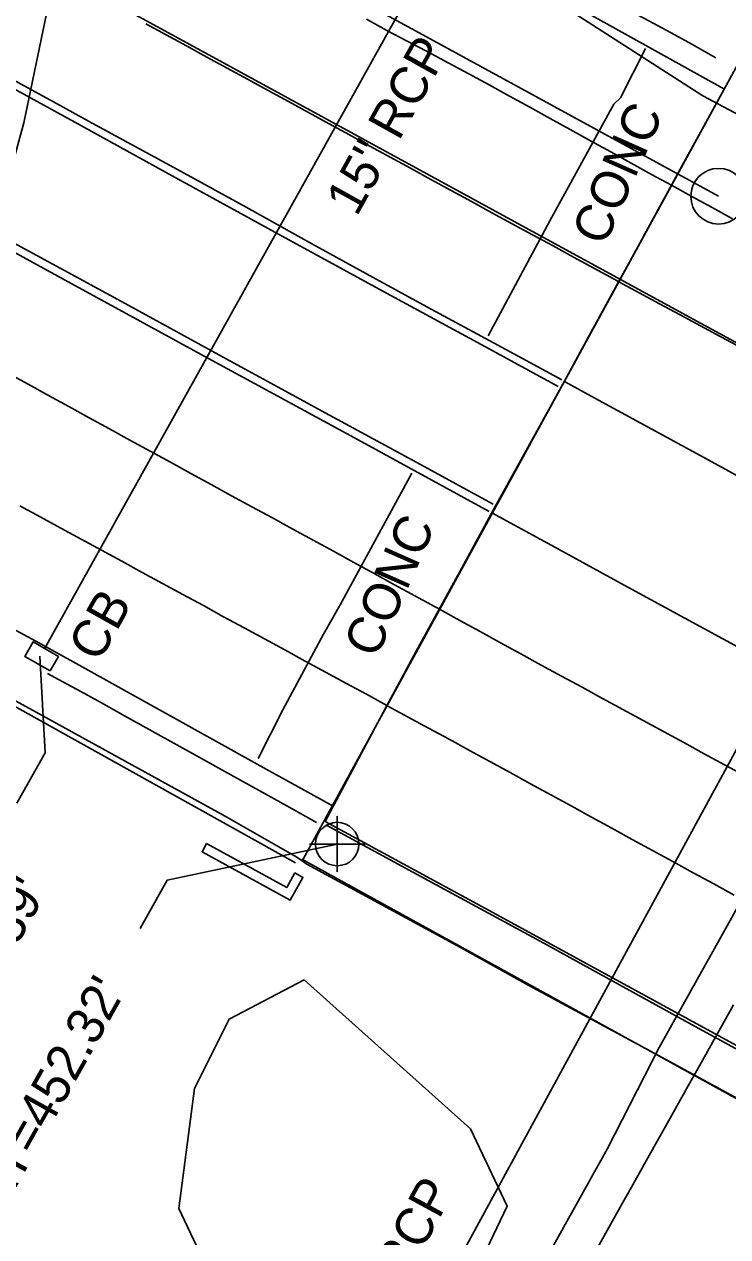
# Model space of a CAD drawing. Extents: x 2074109 to 2077820, y 741079 to 746031.
# Drawn here: x 2075369.9 to 2075445.8, y 743340.7 to 743471.4 of the extents above; entities that cross this region are included whole.
import ezdxf

# ---------------------------------------------------------------- set-up
doc = ezdxf.new("R2010")
doc.units = 0
for name, color, linetype in [('Exist Guardrail', 7, 'Continuous'), ('Exist Horizontal Alignment', 7, 'Continuous'), ('Exist Horizontal Alignment Point', 7, 'Continuous'), ('Exist Roads Change in Surface', 7, 'Continuous'), ('Exist Roads Change in Surface Text', 7, 'Continuous'), ('Exist Roads Curbs', 7, 'Continuous'), ('Exist Roads EOP', 7, 'Continuous'), ('Exist Roads EOP Other', 7, 'Continuous'), ('Exist Roads EOT', 7, 'Continuous'), ('Exist Structure Major Bridge Seam', 7, 'Continuous'), ('Exist Structure Major Bridge Seat Cogo Point CELL', 7, 'Continuous'), ('Exist Structure Major Bridge Seat Leader', 7, 'Continuous'), ('Exist Structure Major Bridge Seat Top Elevation', 7, 'Continuous'), ('Exist Structure Major Deck Tunnel Box Culvert', 7, 'Continuous'), ('Exist Structure Minor Catch Basin', 7, 'Continuous'), ('Exist Structure Minor Catch Basin Leader', 7, 'Continuous'), ('Exist Structure Minor Catch Basin Text', 7, 'Continuous'), ('Exist Structure Minor Head and End Wall', 7, 'Continuous'), ('Exist Structure Minor Pipes RCP 15 Inch', 7, 'Continuous'), ('Exist Structure Minor Pipes RCP 15 Inch Invert', 7, 'Continuous'), ('Exist Structure Minor Pipes RCP 15 Inch Text', 7, 'Continuous'), ('Exist Structure Minor Pipes RCP 36 Inch', 7, 'Continuous'), ('Exist Structure Minor Pipes RCP 36 Inch Text', 7, 'Continuous'), ('Exist Utilities Telephone UG Conduit SUE LOS B', 7, 'Continuous'), ('Exist Utilities Telephone UG FO SUE LOS B', 7, 'Continuous'), ('Exist Vegetation Woods Line', 7, 'Continuous')]:
    doc.layers.add(name, color=color, linetype=linetype)

msp = doc.modelspace()

# ---------------------------------------------------------------- linework, layer by layer
at = {"layer": 'Exist Guardrail'}
msp.add_lwpolyline([(2075399.18, 743381.02), (2075362.55, 743401.44), (2075326.57, 743419.67), (2075290.61, 743437.99), (2075249.28, 743458.82), (2075221.14, 743472.97)], dxfattribs=at)
at = {"layer": 'Exist Horizontal Alignment'}
for p, q in [((2074769.18, 743807.11), (2075920.37, 743178.35)), ((2075444.78, 743452.87), (2075373.12, 743492))]:
    msp.add_line(p, q, dxfattribs=at)
at = {"layer": 'Exist Horizontal Alignment Point'}
msp.add_circle((2075444.78, 743452.87), 3, dxfattribs=at)
at = {"layer": 'Exist Roads Change in Surface'}
for points in [[(2075419.96, 743437.84), (2075426.6, 743450.23), (2075433.48, 743462.79), (2075434.19, 743463.49), (2075436.91, 743468.78)], [(2075411.73, 743423.01), (2075404, 743408.84), (2075402.21, 743405.67), (2075397.81, 743397.52), (2075395.17, 743392.28)]]:
    msp.add_lwpolyline(points, dxfattribs=at)
at = {"layer": 'Exist Roads Curbs'}
for points in [[(2075175.25, 743570.29), (2075183.74, 743565.61), (2075195.08, 743559.37), (2075206.25, 743553.25), (2075217.16, 743547.3), (2075227.86, 743541.4), (2075238.69, 743535.42), (2075250.44, 743529.02), (2075262.94, 743522.24), (2075275.65, 743515.31), (2075288.48, 743508.29), (2075301.25, 743501.33), (2075314, 743494.4), (2075326.85, 743487.38), (2075339.73, 743480.33), (2075352.49, 743473.37), (2075365.03, 743466.54), (2075375.41, 743460.85), (2075385.9, 743455.07), (2075397.36, 743448.78), (2075408.6, 743442.64), (2075420.04, 743436.42), (2075427.48, 743432.37)], [(2075420.48, 743419.7), (2075420.02, 743419.95), (2075412.25, 743424.18), (2075402.85, 743429.29), (2075391.33, 743435.57), (2075380.42, 743441.51), (2075371.29, 743446.47), (2075364.58, 743450.13), (2075360.37, 743452.44), (2075354.18, 743455.85), (2075344.34, 743461.27), (2075334.17, 743466.84), (2075325, 743471.86), (2075315.82, 743476.88), (2075306.25, 743482.12), (2075297.05, 743487.13), (2075288.5, 743491.79), (2075279.47, 743496.71), (2075269.54, 743502.14), (2075259.42, 743507.68), (2075249.44, 743513.13), (2075240.01, 743518.27), (2075231.36, 743522.98)], [(2075417.69, 743482.38), (2075418.53, 743481.88), (2075419.49, 743481.34), (2075420.55, 743480.75), (2075421.73, 743480.12), (2075423.1, 743479.4), (2075424.73, 743478.52), (2075426.61, 743477.5), (2075428.76, 743476.34), (2075430.99, 743475.12), (2075433.14, 743473.96), (2075435.22, 743472.85), (2075436.72, 743472.05), (2075438.18, 743471.28), (2075440.06, 743470.26), (2075441.88, 743469.26), (2075443.64, 743468.26), (2075444.49, 743467.77)], [(2075372.45, 743401.45), (2075374.11, 743400.55), (2075376.06, 743399.49), (2075378.27, 743398.27), (2075380.76, 743396.89), (2075384.07, 743395.06), (2075388.73, 743392.46), (2075391.57, 743390.88), (2075398.26, 743387.16), (2075401.43, 743385.38)]]:
    msp.add_lwpolyline(points, dxfattribs=at)
at = {"layer": 'Exist Roads EOP'}
for points in [[(2075559.5, 743577.98), (2075554.8, 743568.73), (2075547.03, 743553.55), (2075539.18, 743539.38), (2075530.34, 743523.8), (2075517.96, 743501.62), (2075504.54, 743477.52), (2075492.04, 743456), (2075482.7, 743440.16), (2075465.16, 743408.97), (2075448.94, 743380.02), (2075438.36, 743361.14), (2075432.82, 743350.24), (2075423.13, 743332.91), (2075408.43, 743306.71), (2075394.81, 743282.87), (2075378.9, 743255.03), (2075364.05, 743228.71), (2075347.68, 743199.79), (2075332.2, 743172.4), (2075317.22, 743145.53), (2075301.28, 743116.93)], [(2075445.35, 743464.44), (2075424.96, 743475.81), (2075414.28, 743481.69), (2075407.34, 743485.74), (2075396.65, 743492.12), (2075387.15, 743498.07), (2075378.48, 743503.71), (2075370.8, 743508.8), (2075365.1, 743512.76), (2075359.72, 743516.76), (2075352.43, 743522.45), (2075343.87, 743529.41), (2075336.63, 743535.65), (2075330.1, 743541.75), (2075323.4, 743548.45), (2075316.7, 743555.85), (2075309.06, 743565.08), (2075302.29, 743573.79)], [(2075427.87, 743433.07), (2075420.6, 743437.03), (2075413.35, 743440.97), (2075407.54, 743444.13), (2075401.03, 743447.72), (2075393.85, 743451.69), (2075386.06, 743455.97), (2075377.27, 743460.76), (2075372.37, 743463.44), (2075361.94, 743469.13), (2075353.05, 743473.99), (2075345.6, 743478.07), (2075336.55, 743483.02), (2075325.74, 743488.95), (2075315.16, 743494.76), (2075305.01, 743500.33), (2075294.55, 743506.07), (2075283.83, 743511.92), (2075274.03, 743517.26), (2075265.18, 743522.07), (2075256.27, 743526.92), (2075247.15, 743531.89), (2075238.05, 743536.86)], [(2075284.45, 743493.05), (2075292.25, 743488.78), (2075300.07, 743484.51), (2075307.84, 743480.26), (2075315.47, 743476.09), (2075323.04, 743471.96), (2075330.63, 743467.8), (2075338.47, 743463.51), (2075346.79, 743458.93), (2075355.33, 743454.23), (2075363.85, 743449.56), (2075374.69, 743443.65), (2075390.21, 743435.18), (2075405.93, 743426.61), (2075417.36, 743420.37), (2075420.04, 743418.91)], [(2075230.5, 743481.8), (2075255.92, 743467.85), (2075272.88, 743458.6), (2075289.2, 743449.66), (2075307.46, 743439.62), (2075321.84, 743431.78), (2075340.07, 743421.91), (2075360.95, 743410.47), (2075371.58, 743404.7), (2075377.48, 743401.43), (2075396.01, 743391.13), (2075403.25, 743387.13)], [(2075532.37, 743375.92), (2075523.96, 743380.52), (2075515.49, 743385.17), (2075506.78, 743389.94), (2075497.65, 743394.92), (2075489.69, 743399.26), (2075484.47, 743402.11), (2075479.33, 743404.92), (2075471.62, 743409.15), (2075462.56, 743414.11), (2075453.37, 743419.14), (2075443.26, 743424.67), (2075431.45, 743431.12), (2075428.16, 743432.91)], [(2075420.33, 743418.75), (2075426.41, 743415.43), (2075434.98, 743410.75), (2075445.24, 743405.16), (2075459.35, 743397.48), (2075472.97, 743390.06), (2075481.74, 743385.26), (2075488.52, 743381.56), (2075496.16, 743377.42), (2075504.19, 743373.06), (2075512.14, 743368.72), (2075520.42, 743364.18), (2075529.4, 743359.25), (2075538.28, 743354.38)]]:
    msp.add_lwpolyline(points, dxfattribs=at)
at = {"layer": 'Exist Roads EOP Other'}
for points in [[(2075366.87, 743399.63), (2075391.52, 743386.11), (2075399.31, 743381.63), (2075400.42, 743380.9), (2075400.42, 743380.9), (2075417.05, 743371.88), (2075424.34, 743367.81), (2075437.43, 743360.73), (2075449.67, 743354.08), (2075462.75, 743347.04), (2075479.55, 743337.75), (2075493.27, 743330.26), (2075511.78, 743320.13), (2075532.97, 743308.52), (2075543.32, 743302.78), (2075555.58, 743296.07), (2075570.56, 743287.96), (2075581.08, 743282.13), (2075591.83, 743276.3), (2075602.54, 743270.44)], [(2075618.54, 743267.07), (2075601.14, 743276.62), (2075583.53, 743286.17), (2075564.08, 743296.86), (2075539.72, 743310.19), (2075523.4, 743319.09), (2075507.55, 743327.8), (2075492.26, 743336.14), (2075475.25, 743345.43), (2075460.95, 743353.21), (2075441.94, 743363.59), (2075425.56, 743372.59), (2075411.83, 743380.02), (2075402.45, 743385.14)]]:
    msp.add_lwpolyline(points, dxfattribs=at)
at = {"layer": 'Exist Roads EOT'}
for points in [[(2075383.05, 743471.46), (2075385.24, 743470.27), (2075387.44, 743469.07), (2075389.63, 743467.87), (2075391.83, 743466.67), (2075394.02, 743465.47), (2075396.22, 743464.28), (2075398.41, 743463.08), (2075400.6, 743461.88), (2075402.8, 743460.68), (2075404.99, 743459.48), (2075407.18, 743458.28), (2075409.37, 743457.08), (2075411.57, 743455.88), (2075413.76, 743454.68), (2075415.96, 743453.49), (2075418.15, 743452.29), (2075420.35, 743451.1), (2075422.55, 743449.9), (2075424.74, 743448.71), (2075426.94, 743447.51), (2075429.13, 743446.32), (2075431.33, 743445.12), (2075433.53, 743443.93), (2075433.98, 743443.68)], [(2075406.82, 743471.96), (2075409.01, 743470.75), (2075411.22, 743469.58), (2075413.43, 743468.42), (2075415.64, 743467.25), (2075417.85, 743466.08), (2075420.04, 743464.87), (2075422.23, 743463.67), (2075424.42, 743462.46), (2075426.61, 743461.26), (2075428.8, 743460.05), (2075430.99, 743458.85), (2075433.18, 743457.64), (2075435.37, 743456.44), (2075437.56, 743455.23), (2075439.69, 743454.06)], [(2075439.71, 743454.05), (2075441.9, 743452.84), (2075444.09, 743451.64), (2075446.28, 743450.43)], [(2075434.03, 743443.66), (2075436.22, 743442.46), (2075438.42, 743441.27), (2075440.62, 743440.08), (2075442.82, 743438.9), (2075445.03, 743437.72), (2075447.23, 743436.55)], [(2075368.19, 743433.82), (2075370.38, 743432.62), (2075372.57, 743431.41), (2075374.75, 743430.2), (2075376.94, 743428.99), (2075379.14, 743427.79), (2075381.33, 743426.6), (2075383.52, 743425.4), (2075385.72, 743424.2), (2075387.91, 743423), (2075390.11, 743421.8), (2075392.3, 743420.6), (2075394.49, 743419.4), (2075396.69, 743418.21), (2075398.88, 743417.01), (2075401.08, 743415.81), (2075403.27, 743414.61), (2075405.46, 743413.41), (2075407.66, 743412.21), (2075409.85, 743411.01), (2075412.04, 743409.81), (2075414.24, 743408.62), (2075414.65, 743408.39)], [(2075409.01, 743398), (2075406.82, 743399.2), (2075404.62, 743400.39), (2075402.43, 743401.59), (2075400.23, 743402.78), (2075398.03, 743403.98), (2075395.84, 743405.17), (2075393.64, 743406.36), (2075391.44, 743407.56), (2075389.25, 743408.75), (2075387.05, 743409.95), (2075384.86, 743411.14), (2075382.66, 743412.34), (2075380.46, 743413.53), (2075378.27, 743414.73), (2075376.07, 743415.92), (2075373.88, 743417.11), (2075371.68, 743418.31), (2075369.48, 743419.5)], [(2075414.71, 743408.36), (2075416.9, 743407.16), (2075419.09, 743405.96), (2075421.28, 743404.76), (2075423.47, 743403.55), (2075425.67, 743402.35), (2075427.86, 743401.15), (2075430.06, 743399.96), (2075432.25, 743398.76), (2075434.45, 743397.57), (2075436.65, 743396.38), (2075438.84, 743395.18), (2075441.04, 743393.99), (2075443.23, 743392.79), (2075445.43, 743391.6), (2075447.63, 743390.4)], [(2075446.44, 743377.56), (2075444.25, 743378.76), (2075442.05, 743379.96), (2075439.86, 743381.16), (2075437.67, 743382.36), (2075435.47, 743383.56), (2075433.28, 743384.76), (2075431.09, 743385.96), (2075428.89, 743387.16), (2075426.7, 743388.36), (2075424.51, 743389.56), (2075422.31, 743390.76), (2075420.12, 743391.95), (2075417.92, 743393.15), (2075415.73, 743394.35), (2075413.53, 743395.54), (2075411.34, 743396.74), (2075409.14, 743397.93), (2075409.07, 743397.97)], [(2075431.72, 743339.55), (2075432.95, 743341.73), (2075434.17, 743343.91), (2075435.39, 743346.09), (2075436.61, 743348.27), (2075437.84, 743350.45), (2075439.06, 743352.63), (2075440.28, 743354.81), (2075441.5, 743356.99), (2075442.72, 743359.17), (2075443.94, 743361.36), (2075445.17, 743363.54), (2075446.39, 743365.72)]]:
    msp.add_lwpolyline(points, dxfattribs=at)
at = {"layer": 'Exist Structure Major Bridge Seam'}
msp.add_line((2075448.73, 743470.53), (2075400.01, 743381.42), dxfattribs=at)
at = {"layer": 'Exist Structure Major Bridge Seat Cogo Point CELL'}
msp.add_lwpolyline([(2075400.68, 743383.06), (2075406.68, 743383.06), (2075403.68, 743383.06), (2075403.68, 743386.06), (2075403.68, 743380.06)], dxfattribs=at)
msp.add_circle((2075403.68, 743383.06), 2.34, dxfattribs=at)
at = {"layer": 'Exist Structure Major Bridge Seat Leader'}
msp.add_lwpolyline([(2075403.68, 743383.06), (2075385.36, 743379.17), (2075382.43, 743373.94)], dxfattribs=at)
at = {"layer": 'Exist Structure Major Deck Tunnel Box Culvert'}
msp.add_line((2075625.56, 743257.09), (2075399.85, 743381.42), dxfattribs=at)
msp.add_lwpolyline([(2075447.11, 743361.12), (2075420.46, 743375.68), (2075402.38, 743385.5), (2075408.96, 743397.83), (2075411.14, 743401.89), (2075412.24, 743403.92), (2075412.38, 743404.17), (2075416.85, 743412.36), (2075419.54, 743417.31), (2075420.26, 743418.63), (2075428.38, 743433.32), (2075428.94, 743434.36), (2075431.21, 743438.59), (2075432.87, 743441.61), (2075436.25, 743447.76), (2075436.79, 743448.75), (2075436.96, 743449.06), (2075441.26, 743456.9), (2075446.35, 743466.17)], dxfattribs=at)
at = {"layer": 'Exist Structure Minor Catch Basin'}
msp.add_lwpolyline([(2075372.75, 743401.71), (2075370.01, 743403.28), (2075370.91, 743404.84), (2075373.64, 743403.26)], close=True, dxfattribs=at)
at = {"layer": 'Exist Structure Minor Catch Basin Leader'}
msp.add_lwpolyline([(2075371.62, 743403.32), (2075372.2, 743392.88), (2075369.15, 743387.46)], dxfattribs=at)
at = {"layer": 'Exist Structure Minor Head and End Wall'}
for points in [[(2075399.11, 743379.96), (2075399.98, 743379.47), (2075398.62, 743377.02), (2075389.11, 743382.23), (2075389.59, 743383.11)], [(2075399.11, 743379.96), (2075398.23, 743378.37), (2075389.59, 743383.11)]]:
    msp.add_lwpolyline(points, dxfattribs=at)
at = {"layer": 'Exist Structure Minor Pipes RCP 15 Inch'}
msp.add_line((2075372.17, 743404.16), (2075415.09, 743481.19), dxfattribs=at)
at = {"layer": 'Exist Structure Minor Pipes RCP 36 Inch'}
msp.add_line((2075364.8, 743242.78), (2075501.91, 743494.72), dxfattribs=at)
at = {"layer": 'Exist Utilities Telephone UG Conduit SUE LOS B'}
msp.add_lwpolyline([(2074852.23, 743796.93), (2074858.98, 743788.14), (2074871.16, 743780.09), (2074884.61, 743773.35), (2074910.14, 743759.3), (2074929.12, 743745.39), (2074958.42, 743728.87), (2074997.61, 743706.69), (2075052.29, 743677.02), (2075084.82, 743660.77), (2075107.9, 743645.87), (2075165.73, 743622.21), (2075198.81, 743604.97), (2075246.84, 743581.99), (2075289.9, 743561.06), (2075322.06, 743548.08), (2075339.73, 743539.52), (2075355.79, 743530.19), (2075360.13, 743528.64), (2075373.71, 743515.02), (2075393.05, 743495.87), (2075443.09, 743463.69), (2075672.89, 743341.39)], dxfattribs=at)
at = {"layer": 'Exist Utilities Telephone UG FO SUE LOS B'}
msp.add_lwpolyline([(2075222.87, 743080.84), (2075256.4, 743137.17), (2075288.87, 743193.63), (2075300.42, 743220.4), (2075312.11, 743252.93), (2075313.41, 743275.26), (2075321.97, 743323.29), (2075330.4, 743351.2), (2075353.35, 743389.78), (2075353.46, 743389.59), (2075359.52, 743410.61), (2075366.87, 743449.87), (2075369.9, 743460.77), (2075379.26, 743505.72), (2075382.17, 743515.51), (2075388.11, 743522.63), (2075396.38, 743532.84), (2075411.7, 743544.41), (2075448.92, 743560.88), (2075483.77, 743574.68)], dxfattribs=at)
at = {"layer": 'Exist Vegetation Woods Line'}
msp.add_lwpolyline([(2075400.11, 743368.42), (2075418.03, 743352.36), (2075421.98, 743344.02), (2075414.98, 743329.35), (2075408.95, 743320), (2075395.05, 743325.94), (2075386.61, 743343.77), (2075388.31, 743356.73), (2075392.05, 743364.2), (2075400.11, 743368.42)], dxfattribs=at)

# ---------------------------------------------------------------- texts
at = {"layer": 'Exist Roads Change in Surface Text'}
for p in [(2075432.48, 743447.36), (2075407.9, 743402.94)]:
    msp.add_text('CONC', height=4, rotation=66.0514, dxfattribs=at).set_placement(p)
at = {"layer": 'Exist Structure Major Bridge Seat Top Elevation'}
msp.add_text("SEAT=452.32'", height=4, rotation=60.742, dxfattribs=at).set_placement((2075364.14, 743337.2))
at = {"layer": 'Exist Structure Minor Catch Basin Text'}
msp.add_text('CB', height=4, rotation=60.742, dxfattribs=at).set_placement((2075378, 743402.51))
at = {"layer": 'Exist Structure Minor Pipes RCP 15 Inch Invert'}
msp.add_text("INV OUT=455.39'", height=4, rotation=60.8285, dxfattribs=at).set_placement((2075351.96, 743341.22))
at = {"layer": 'Exist Structure Minor Pipes RCP 15 Inch Text'}
msp.add_text('15" RCP', height=4, rotation=60.868, dxfattribs=at).set_placement((2075405.77, 743450.58))
at = {"layer": 'Exist Structure Minor Pipes RCP 36 Inch Text'}
msp.add_text('36" RCP', height=4, rotation=61.4446, dxfattribs=at).set_placement((2075406.49, 743327.55))

doc.saveas('drawing.dxf')
